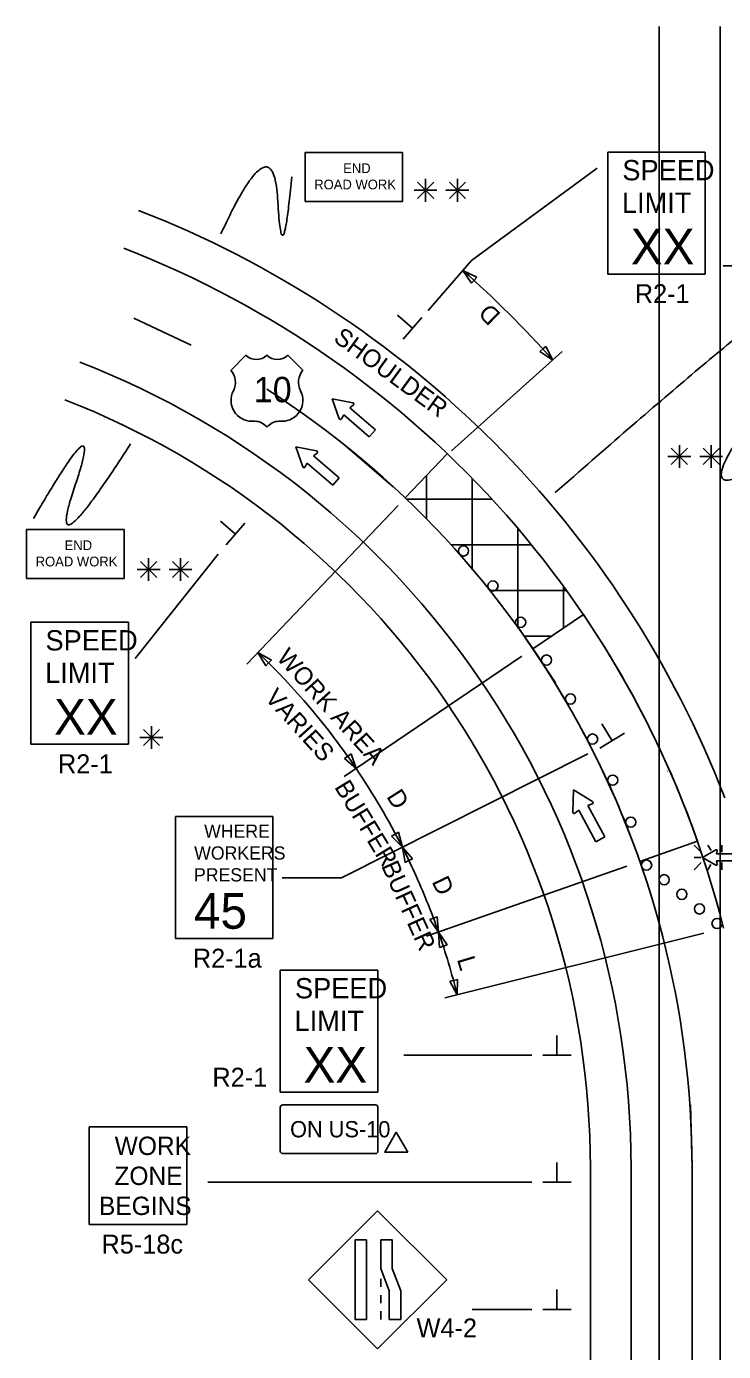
# Model space of a CAD drawing. Extents: x 16303 to 18475, y 5704 to 6974.
# Drawn here: x 16732 to 17006, y 6453 to 6974 of the extents above; entities that cross this region are included whole.
import ezdxf

# ---------------------------------------------------------------- set-up
doc = ezdxf.new("R2010")
doc.units = 0
for name, color, linetype in [('ALI_LEGAL_EX', 7, 'Continuous'), ('MT_SCRATCH_LEVEL_A', 7, 'Continuous'), ('MT_SCRATCH_LEVEL_E', 7, 'Continuous'), ('PAVT_EDGE_EX', 7, 'Continuous'), ('TRAFFIC_SIGNS_PR', 7, 'Continuous'), ('TYPICAL_EX', 7, 'Continuous'), ('TYPICAL_TEXT_DIMEN_PR', 7, 'Continuous')]:
    doc.layers.add(name, color=color, linetype=linetype)

msp = doc.modelspace()

# ---------------------------------------------------------------- linework, layer by layer
at = {"layer": 'ALI_LEGAL_EX'}
for p, q in [((16980.68, 6974.12), (16980.68, 6155.98)), ((17004.68, 6974.12), (17004.68, 6155.98)), ((16980.68, 6877.04), (16980.68, 6013.12)), ((17004.68, 6877.04), (17004.68, 6013.12)), ((16993.65, 6024.8), (16993.65, 6525.15))]:
    msp.add_line(p, q, dxfattribs=at)
for points in [[(17004.68, 6949.12), (17004.68, 6974.12)], [(16796.64, 6848.72), (16773.99, 6859.31)], [(16876.06, 6792.99), (16857.11, 6809.3)], [(16939.89, 6715.82), (16925.99, 6736.59)], [(16993.6, 6524.8), (16993.65, 6525.15), (16993.08, 6549.79)]]:
    msp.add_lwpolyline(points, dxfattribs=at)
msp.add_arc((16629.65, 6525.15), 364, 0, 57.2958, dxfattribs=at)
at = {"layer": 'MT_SCRATCH_LEVEL_A'}
for p, q in [((16889.15, 6780.44), (16889.15, 6797.39)), ((16907.15, 6760.43), (16907.15, 6796.32)), ((16881.28, 6788.2), (16914.86, 6788.2)), ((16925.15, 6737.43), (16925.15, 6776.33)), ((16898.84, 6770.2), (16930.27, 6770.2)), ((16914.07, 6752.2), (16944.07, 6752.2)), ((16943.15, 6737.46), (16943.15, 6753.45)), ((16927.54, 6734.2), (16938.34, 6734.2)), ((16984.05, 6681.24), (16984.1, 6681.16)), ((16995.8, 6653.51), (16973.15, 6645.57)), ((16973.15, 6645.57), (16995.8, 6653.51))]:
    msp.add_line(p, q, dxfattribs=at)
at = {"layer": 'MT_SCRATCH_LEVEL_E'}
for p, q in [((16860.24, 6826.04), (16852.05, 6827.62)), ((16852.05, 6827.62), (16854.86, 6819.78)), ((16859.05, 6824.09), (16860.45, 6825.23)), ((16855.69, 6819.7), (16856.61, 6821.26)), ((16856.61, 6821.26), (16866.66, 6812.61)), ((16869.1, 6815.45), (16859.05, 6824.09)), ((16866.66, 6812.61), (16869.1, 6815.45)), ((16845.92, 6807.1), (16837.72, 6808.67)), ((16837.72, 6808.67), (16840.53, 6800.84)), ((16844.72, 6805.15), (16846.12, 6806.29)), ((16854.77, 6796.5), (16844.72, 6805.15)), ((16841.36, 6800.76), (16842.28, 6802.31)), ((16842.28, 6802.31), (16852.33, 6793.66)), ((16852.33, 6793.66), (16854.77, 6796.5))]:
    msp.add_line(p, q, dxfattribs=at)
for centre, start, end in [((16860.15, 6825.59), 309.3361, 79.073), ((16855.3, 6819.95), 199.7248, 329.2637), ((16845.82, 6806.64), 309.3361, 79.073), ((16840.97, 6801), 199.7248, 329.2637)]:
    msp.add_arc(centre, 0.463, start, end, dxfattribs=at)
at = {"layer": 'PAVT_EDGE_EX'}
for p, q in [((16950.92, 6742.72), (16931.04, 6729.25)), ((16973.16, 6645.58), (16995.81, 6653.52)), ((16953.65, 6525.15), (16953.65, 6062.71)), ((16969.65, 6525.15), (16969.65, 6062.71))]:
    msp.add_line(p, q, dxfattribs=at)
for centre, radius, start, end in [((16629.65, 6525.15), 404, 21.0961, 68.7791), ((16629.65, 6525.15), 388, 14.0482, 68.7791), ((16629.65, 6525.15), 340, 0, 68.7791), ((16629.65, 6525.15), 324, 0, 68.7791), ((16629.66, 6525.15), 388, 19.3199, 34.1071), ((16629.66, 6525.15), 363.99, 19.32, 34.1071)]:
    msp.add_arc(centre, radius, start, end, dxfattribs=at)
at = {"layer": 'TRAFFIC_SIGNS_PR'}
for p, q in [((16960.48, 6924.73), (16998.88, 6924.73)), ((16960.48, 6876.73), (16960.48, 6924.73)), ((16998.88, 6876.73), (16998.88, 6924.73)), ((16960.48, 6876.73), (16998.88, 6876.73)), ((16733.5, 6739.74), (16771.9, 6739.74)), ((16733.5, 6691.74), (16733.5, 6739.74)), ((16771.9, 6691.74), (16771.9, 6739.74)), ((16733.5, 6691.74), (16771.9, 6691.74)), ((16790.37, 6663.24), (16828.77, 6663.24)), ((16790.37, 6615.24), (16790.37, 6663.24)), ((16828.77, 6615.24), (16828.77, 6663.24)), ((16994.48, 6652.01), (16997.3, 6649.19)), ((17001.2, 6649.83), (16999.94, 6652.01)), ((17005.38, 6649.19), (17005.38, 6652.01)), ((16997.3, 6647.16), (16994.48, 6647.16)), ((16994.48, 6642.31), (16997.3, 6645.13)), ((16999.91, 6642.31), (17001.12, 6644.4)), ((17005.38, 6645.13), (17005.38, 6642.31)), ((16790.37, 6615.24), (16828.77, 6615.24)), ((16831.66, 6602.83), (16870.06, 6602.83)), ((16831.66, 6554.83), (16831.66, 6602.83)), ((16870.06, 6554.83), (16870.06, 6602.83)), ((16831.66, 6554.83), (16870.06, 6554.83)), ((16831.66, 6548.83), (16831.66, 6531.63)), ((16832.66, 6549.83), (16869.06, 6549.83)), ((16870.06, 6548.83), (16870.06, 6531.63)), ((16756.48, 6502.73), (16756.48, 6541.13)), ((16756.48, 6541.13), (16794.88, 6541.13)), ((16794.88, 6502.73), (16794.88, 6541.13)), ((16832.66, 6530.63), (16869.06, 6530.63)), ((16869.96, 6508.06), (16842.81, 6480.9)), ((16897.12, 6480.9), (16869.96, 6508.06)), ((16756.48, 6502.73), (16794.88, 6502.73)), ((16842.81, 6480.9), (16869.96, 6453.75)), ((16869.96, 6453.75), (16897.12, 6480.9)), ((16871.2, 6481.39), (16871.2, 6478.19)), ((16871.2, 6474.99), (16871.2, 6471.79)), ((16871.2, 6468.59), (16871.2, 6465.39))]:
    msp.add_line(p, q, dxfattribs=at)
for points in [[(16841.39, 6905.3), (16879.79, 6905.3), (16879.79, 6924.5), (16841.39, 6924.5)], [(16731.78, 6756.94), (16770.18, 6756.94), (16770.18, 6776.14), (16731.78, 6776.14)], [(16861.07, 6496.64), (16861.07, 6465.39), (16865.56, 6465.39), (16865.56, 6496.64)], [(16871.2, 6496.64), (16871.2, 6485.46), (16874.55, 6476.58), (16874.55, 6465.39), (16879.04, 6465.39), (16879.04, 6476.58), (16875.7, 6485.46), (16875.7, 6496.64)]]:
    msp.add_lwpolyline(points, close=True, dxfattribs=at)
for points in [[(17003.05, 6650.18), (16997.74, 6647.16), (17003.05, 6644.12)], [(17003.55, 6644.48), (17003.32, 6645.78), (17013.05, 6645.78), (17013.05, 6648.52), (17003.32, 6648.52), (17003.56, 6649.82)]]:
    msp.add_lwpolyline(points, dxfattribs=at)
for centre in [(16903.73, 6767.76), (16915.33, 6753.99), (16926.23, 6739.67), (16936.42, 6724.84), (16945.86, 6709.51), (16954.54, 6693.75), (16962.44, 6677.57), (16969.53, 6661.03), (16975.8, 6644.16), (16982.72, 6638.4), (16989.65, 6632.65), (16996.57, 6626.9), (17003.5, 6621.15)]:
    msp.add_circle(centre, 2, dxfattribs=at)
for centre, radius, start, end in [((17003.22, 6649.88), 0.341, 350.7308, 118.8916), ((17003.22, 6644.42), 0.341, 241.4833, 9.9593), ((16832.66, 6548.83), 1, 90, 180), ((16869.06, 6548.83), 1, 0, 90), ((16832.66, 6531.63), 1, 180, 270), ((16869.06, 6531.63), 1, 270, 0)]:
    msp.add_arc(centre, radius, start, end, dxfattribs=at)
at = {"layer": 'TYPICAL_EX'}
for p, q in [((16812.25, 6838.84), (16818.14, 6844.74)), ((16840.55, 6838.84), (16834.65, 6844.74)), ((16820.49, 6818.78), (16821.67, 6818.78)), ((16832.3, 6818.78), (16831.12, 6818.78))]:
    msp.add_line(p, q, dxfattribs=at)
for centre, radius, start, end in [((16822.27, 6849.03), 5.96, 226.1404, 313.8596), ((16830.52, 6849.03), 5.96, 226.1404, 313.8596), ((16806.66, 6834.12), 7.31, 333.0977, 40.1936), ((16846.13, 6834.12), 7.31, 139.8064, 206.9023), ((16820.51, 6827.03), 8.24, 152.6698, 269.9013), ((16832.29, 6827.03), 8.24, 270.0987, 27.3302), ((16821.69, 6812.88), 5.91, 37.1038, 90.1385), ((16831.11, 6812.88), 5.91, 89.8615, 142.8962)]:
    msp.add_arc(centre, radius, start, end, dxfattribs=at)
at = {"layer": 'TYPICAL_TEXT_DIMEN_PR'}
for p, q in [((16888.81, 6909.67), (16888.81, 6914.13)), ((16901.37, 6909.67), (16901.37, 6914.13)), ((16906.84, 6882.01), (16956.27, 6918.43)), ((16888.81, 6909.67), (16884.28, 6909.67)), ((16892, 6912.86), (16885.62, 6906.48)), ((16885.63, 6912.86), (16892, 6906.48)), ((16888.81, 6909.67), (16892, 6909.67)), ((16888.81, 6909.67), (16893.29, 6909.67)), ((16888.81, 6909.67), (16888.81, 6905.17)), ((16901.37, 6909.67), (16896.84, 6909.67)), ((16898.18, 6912.86), (16904.56, 6906.48)), ((16904.56, 6912.86), (16898.18, 6906.48)), ((16901.37, 6909.67), (16904.56, 6909.67)), ((16901.37, 6909.67), (16905.85, 6909.67)), ((16901.37, 6909.67), (16901.37, 6905.17)), ((16906.84, 6882.01), (16889.86, 6862.32)), ((16906.94, 6873.15), (16903.53, 6878.17)), ((16903.53, 6878.17), (16908.99, 6875.53)), ((17010.46, 6879.91), (17005.93, 6879.91)), ((16907.97, 6874.34), (16906.94, 6873.15)), ((16908.99, 6875.53), (16907.97, 6874.34)), ((16883.67, 6855.4), (16877.78, 6860.48)), ((16887.35, 6859.66), (16880, 6851.14)), ((16942.62, 6846.2), (16898.95, 6807.09)), ((16933.81, 6846.18), (16934.98, 6847.23)), ((16938.89, 6842.86), (16933.81, 6846.18)), ((16934.98, 6847.23), (16936.15, 6848.27)), ((16936.15, 6848.27), (16938.89, 6842.86)), ((16988.67, 6804.97), (16988.67, 6809.42)), ((17001.22, 6804.97), (17001.22, 6809.42)), ((16897.36, 6806), (16880.94, 6788.78)), ((16988.67, 6804.97), (16984.13, 6804.97)), ((16985.48, 6808.15), (16991.85, 6801.78)), ((16991.85, 6808.15), (16985.48, 6801.78)), ((16988.67, 6804.97), (16991.85, 6804.97)), ((16988.67, 6804.97), (16993.14, 6804.97)), ((16988.67, 6804.97), (16988.67, 6800.47)), ((17001.22, 6804.97), (16996.69, 6804.97)), ((17004.41, 6808.15), (16998.03, 6801.78)), ((16998.04, 6808.15), (17004.41, 6801.78)), ((17001.22, 6804.97), (17004.41, 6804.97)), ((17001.22, 6804.97), (17005.7, 6804.97)), ((17001.22, 6804.97), (17001.22, 6800.47)), ((16878, 6785.69), (16818.44, 6723.2)), ((16814.02, 6774.38), (16808.12, 6779.47)), ((16817.69, 6778.64), (16810.34, 6770.12)), ((16807.26, 6766.55), (16774.6, 6725.45)), ((16776.66, 6763.62), (16783.03, 6757.25)), ((16783.03, 6763.62), (16776.66, 6757.25)), ((16779.85, 6760.44), (16779.85, 6764.89)), ((16789.21, 6763.62), (16795.59, 6757.25)), ((16795.59, 6763.62), (16789.21, 6757.25)), ((16792.4, 6760.44), (16792.4, 6764.89)), ((16779.85, 6760.44), (16775.31, 6760.44)), ((16779.85, 6760.44), (16783.03, 6760.44)), ((16779.85, 6760.44), (16784.32, 6760.44)), ((16779.85, 6760.44), (16779.85, 6755.94)), ((16792.4, 6760.44), (16787.87, 6760.44)), ((16792.4, 6760.44), (16795.59, 6760.44)), ((16792.4, 6760.44), (16796.88, 6760.44)), ((16792.4, 6760.44), (16792.4, 6755.94)), ((16825.93, 6722.6), (16822.84, 6727.82)), ((16822.84, 6727.82), (16828.13, 6724.85)), ((16926.69, 6726.31), (16856.79, 6678.97)), ((16827.03, 6723.73), (16825.93, 6722.6)), ((16828.13, 6724.85), (16827.03, 6723.73)), ((16962.24, 6693.1), (16958.2, 6699.76)), ((16780.95, 6694.34), (16776.42, 6694.34)), ((16777.76, 6697.53), (16784.14, 6691.15)), ((16784.14, 6697.53), (16777.76, 6691.15)), ((16780.95, 6694.34), (16780.95, 6698.8)), ((16780.95, 6694.34), (16784.14, 6694.34)), ((16780.95, 6694.34), (16785.43, 6694.34)), ((16780.95, 6694.34), (16780.95, 6689.84)), ((16967.05, 6696.02), (16957.43, 6690.18)), ((16952.72, 6687.99), (16855.78, 6639.12)), ((16856.89, 6686.12), (16858.19, 6687)), ((16861.49, 6682.15), (16856.89, 6686.12)), ((16858.19, 6687), (16859.49, 6687.88)), ((16859.49, 6687.88), (16861.49, 6682.15)), ((16946.96, 6673.82), (16946.8, 6664.94)), ((16954.53, 6669.15), (16946.96, 6673.82)), ((16952.61, 6667.66), (16954.43, 6668.27)), ((16947.6, 6664.55), (16949.1, 6665.75)), ((16949.1, 6665.75), (16955.86, 6653.33)), ((16959.37, 6655.24), (16952.61, 6667.66)), ((16875.44, 6655.51), (16876.81, 6656.28)), ((16879.68, 6651.17), (16875.44, 6655.51)), ((16876.81, 6656.28), (16878.17, 6657.05)), ((16878.17, 6657.05), (16879.68, 6651.17)), ((16955.86, 6653.33), (16959.37, 6655.24)), ((16880.84, 6645.21), (16879.68, 6651.17)), ((16879.68, 6651.17), (16883.66, 6646.59)), ((16882.25, 6645.9), (16880.84, 6645.21)), ((16883.66, 6646.59), (16882.25, 6645.9)), ((16968.07, 6643.79), (16889.16, 6616.13)), ((16855.78, 6639.12), (16832.39, 6639.08)), ((16890.46, 6622.79), (16891.94, 6623.31)), ((16893.88, 6617.78), (16890.46, 6622.79)), ((16891.94, 6623.31), (16893.42, 6623.83)), ((16893.42, 6623.83), (16893.88, 6617.78)), ((16894.34, 6611.73), (16893.88, 6617.78)), ((16893.88, 6617.78), (16897.3, 6612.77)), ((16998.34, 6617.4), (16896.42, 6591.9)), ((16895.82, 6612.25), (16894.34, 6611.73)), ((16897.3, 6612.77), (16895.82, 6612.25)), ((16898.33, 6598.42), (16899.85, 6598.8)), ((16901.28, 6593.11), (16898.33, 6598.42)), ((16899.85, 6598.8), (16901.38, 6599.18)), ((16901.38, 6599.18), (16901.28, 6593.11)), ((16940.52, 6569.33), (16940.52, 6577.11)), ((16930.65, 6569.33), (16880.28, 6569.33)), ((16934.9, 6569.33), (16946.15, 6569.33)), ((16940.52, 6519.33), (16940.52, 6527.11)), ((16930.65, 6519.33), (16803.17, 6519.33)), ((16934.9, 6519.33), (16946.15, 6519.33)), ((16940.52, 6469.33), (16940.52, 6477.11)), ((16930.65, 6469.33), (16907.2, 6469.33)), ((16934.9, 6469.33), (16946.15, 6469.33))]:
    msp.add_line(p, q, dxfattribs=at)
msp.add_lwpolyline([(16877.26, 6539.08), (16872.74, 6531.24), (16881.79, 6531.24)], close=True, dxfattribs=at)
for centre, radius, start, end in [((16605.17, 6543.98), 448, 41.8471, 48.2417), ((16629.65, 6525.15), 280, 34.1071, 46.3726), ((16629.65, 6525.15), 280, 26.7494, 34.1071), ((16954.26, 6668.74), 0.494, 288.5864, 58.3233), ((16947.29, 6664.94), 0.494, 178.9751, 308.514), ((16629.65, 6525.15), 280, 24.1124, 26.7494), ((16629.65, 6525.15), 280, 19.32, 24.1124), ((16629.65, 6525.15), 280, 14.0482, 19.32)]:
    msp.add_arc(centre, radius, start, end, dxfattribs=at)
for points in [[(16808.29, 6892.58), (16828.92, 6937.4), (16832.37, 6874.05), (16836.14, 6914.93)], [(17147.1, 6896.49), (16938.05, 6725.63), (17135.55, 6962.67), (16939.82, 6790.7)], [(16772.76, 6809.91), (16738.2, 6756.06), (16763.39, 6830.38), (16734.53, 6780.52)]]:
    msp.add_open_spline(points, degree=2, dxfattribs=at)

# ---------------------------------------------------------------- texts
at = {"layer": 'TRAFFIC_SIGNS_PR'}
for s, height, p in [('END', 3.831, (16856.39, 6916.43)), ('SPEED', 8, (16966.24, 6913.59)), ('ROAD WORK', 3.831, (16845, 6910.04)), ('LIMIT', 8, (16966.08, 6900.79)), ('XX', 14.031, (16969.59, 6880.48)), ('R2-1', 7.44, (16971.15, 6865.29)), ('END', 3.831, (16746.78, 6768.07)), ('ROAD WORK', 3.831, (16735.39, 6761.68)), ('SPEED', 8, (16739.26, 6728.6)), ('LIMIT', 8, (16739.1, 6715.8)), ('XX', 14.031, (16742.61, 6695.49)), ('R2-1', 7.44, (16744.17, 6680.3)), ('WHERE', 5.2, (16801.68, 6654.92)), ('WORKERS', 5.2, (16797.76, 6646.32)), ('PRESENT', 5.2, (16797.69, 6637.72)), ('45', 14.031, (16797.68, 6619.1)), ('R2-1a', 7.44, (16797.23, 6603.8)), ('SPEED', 8, (16837.43, 6591.7)), ('LIMIT', 8, (16837.27, 6578.9)), ('XX', 14.031, (16840.78, 6558.59)), ('R2-1', 7.44, (16804.94, 6556.97)), ('ON US-10', 6.4, (16835.5, 6537.03)), ('WORK', 7.217, (16766.48, 6530.09)), ('ZONE', 7.217, (16766.37, 6518.28)), ('BEGINS', 7.217, (16760.29, 6506.47)), ('R5-18c', 7.44, (16761.3, 6491.29)), ('W4-2', 7.44, (16885.28, 6458.31))]:
    msp.add_text(s, height=height, dxfattribs=at).set_placement(p)
at = {"layer": 'TYPICAL_EX'}
msp.add_text('10', height=10, dxfattribs=at).set_placement((16821.24, 6826.27))
at = {"layer": 'TYPICAL_TEXT_DIMEN_PR'}
for s, rotation, p in [('D', 135.5356, (16918.8, 6860.93)), ('SHOULDER', 323.9582, (16852.15, 6850.54)), ('WORK AREA', 312.0857, (16829.86, 6725.49)), ('VARIES', 312.0857, (16825.26, 6709.7)), ('BUFFER', 301.2915, (16852.75, 6674.87)), ('D', 302.4429, (16873.2, 6671.12)), ('BUFFER', 294.3385, (16871.26, 6643.87)), ('D', 295.49, (16891.12, 6637.67)), ('L', 286.685, (16901.1, 6607.13))]:
    msp.add_text(s, height=7, rotation=rotation, dxfattribs=at).set_placement(p)

doc.saveas('drawing.dxf')
